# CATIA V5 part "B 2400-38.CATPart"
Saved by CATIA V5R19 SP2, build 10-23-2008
Part number: B 2400-38
Bounding box of the stored display mesh (mm): x -37.351 to 37.351, y -37.351 to 37.351, z 0 to 186
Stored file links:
  C:\Users\Bora\Desktop\3D Katı model\B serisi\B 2400\B 2400-38.CATPart
  C:\Program Files\Dassault Systemes\B19\intel_a\reffiles\standard\MetricThickPitch.txt
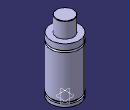
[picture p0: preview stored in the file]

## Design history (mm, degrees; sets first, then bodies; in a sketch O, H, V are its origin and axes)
Body1 (main body)
  Sketch1 on yz-plane, origin (0, 0, 0), H (0, 1, 0), V (0, 0, 1)
    point P3 (22.5, 185)
    point P5 (22.5, 185)
    point P10 (37.5, 124.5)
    point P11 (37.5, 129.5)
    point P13 (37.5, 129.5)
    point P14 (37.5, 124.5)
    line L1 (37.5, 0) -> (37.5, 8)
    line L2 (22.5, 185) -> (22.5, 145)
    arc A1 centre (21.5, 185) radius 1 from (22.5, 185) to (21.5, 186) ccw
    line L3 (33.5, 13) -> (33.5, 8)
    line L4 (37.5, 13) -> (37.5, 124.5)
    line L5 (37.5, 129.5) -> (37.5, 145)
    arc A2 centre (37.5, 127) radius 2.5 from (37.5, 129.5) to (37.5, 124.5) ccw
    line L6 (21.5, 186) -> (0, 186)
    point P15 (0, 186)
    line L7 (22.5, 145) -> (37.5, 145)
    line L8 (0, 0) -> (37.5, 0)
    line L9 (33.5, 13) -> (37.5, 13)
    line L10 (33.5, 8) -> (37.5, 8)
    coincidence: P15 V, P3 P5, P10 P14, P11 P13
    tangency: L6 A1
    horizontal: L7 H, L8 H, L9 H, L10 H
  Shaft1: profile Sketch1, axis Sketch1.V, angle 360
  Sketch2 on face of Shaft1 from Sketch1.L8, origin (0, 0, 0), H (1, 0, 0), V (0, -1, 0)
    point P1 (20, 0)
    distance P1 V = 20
  Hole1: placed by Sketch2, at (20, 0, 0) direction (0, 0, 1), diameter 6.647, depth 13, threaded "M8", thread diameter 8, thread depth 13, pitch 1.25
  CircPattern1: of Hole1, instances 4, angular step 90, axis from xy-plane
